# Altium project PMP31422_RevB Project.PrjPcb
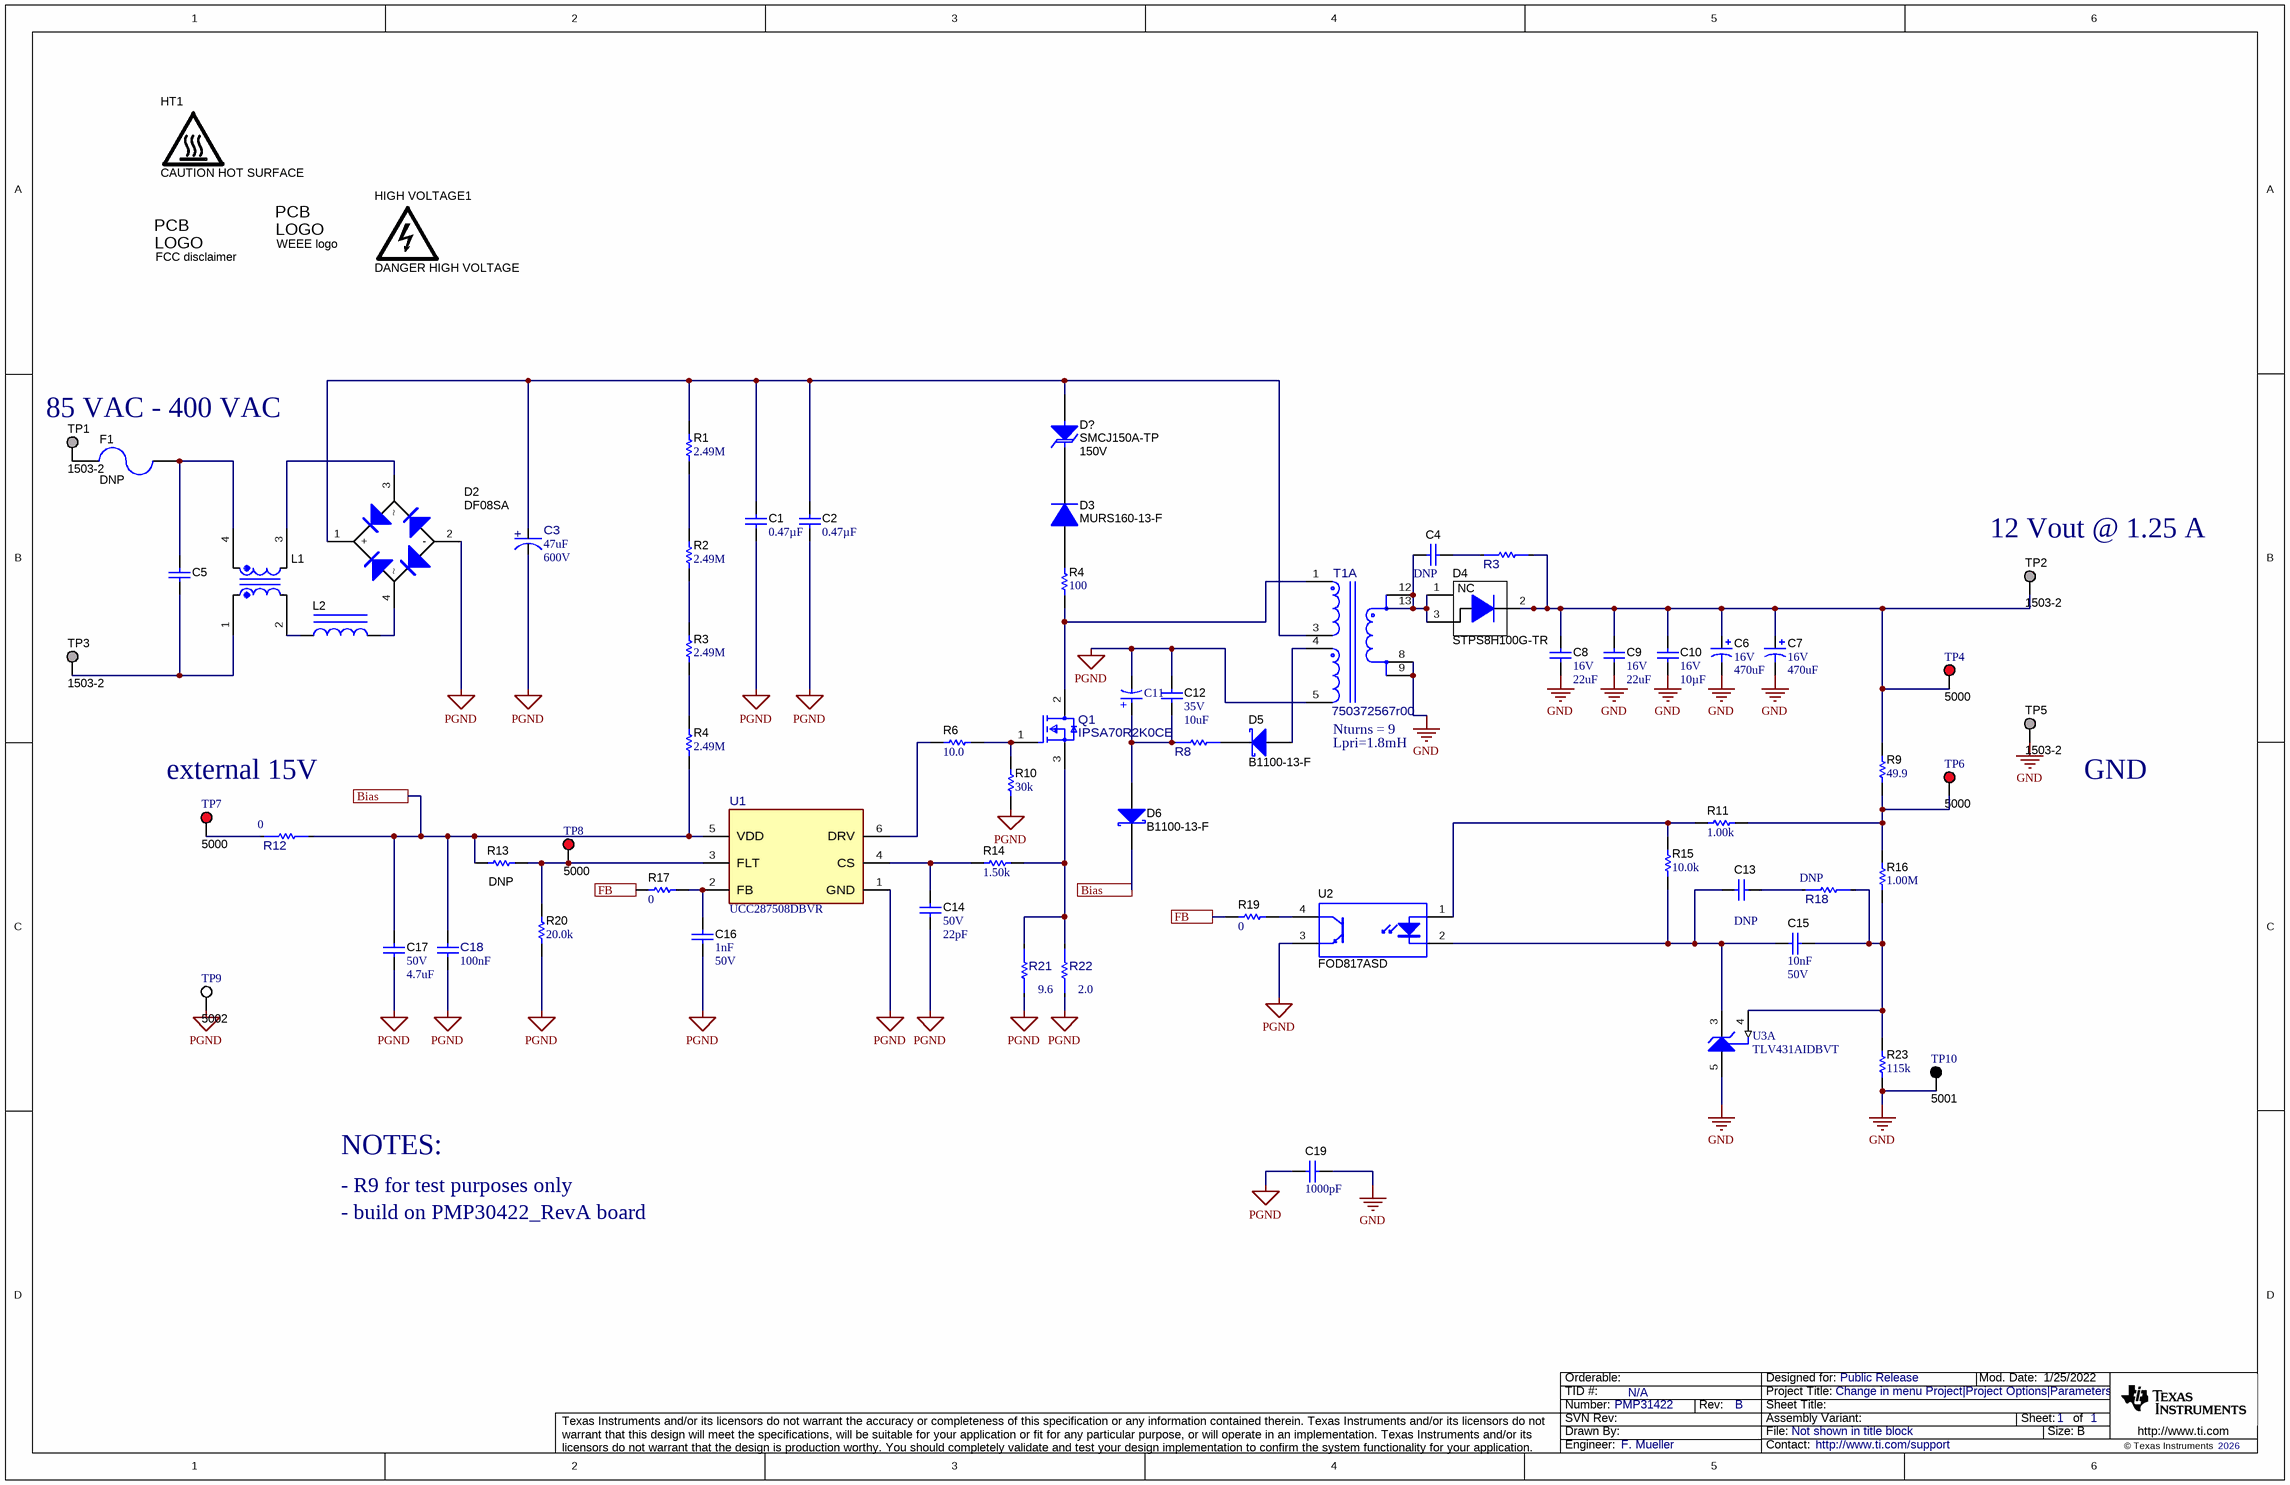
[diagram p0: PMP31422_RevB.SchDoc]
TID: N/A; TechSupport: http://www.ti.com/support; SCH_Rev: B; PRJ_Title: Change in menu Project|Project Options|Parameters; PRJ_Number: PMP31422; PRJ_Engineer: F. Mueller; PRJ_Customer: Public Release; PCB_Rev: A; PCB_Layout: F. Mueller; CopyrightYear: 2026
1 sheet, 70 parts. Net scope: flat (ports and power ports of the same name join across sheets).
Board file: PMP31422_RevA.PcbDoc

## Sheet PMP31422_RevB.SchDoc
size 431 x 279 mm; Date: Not shown in title block; ApprovedBy: Not shown in title block; CheckedBy: Not shown in title block; Author: Not shown in title block; CompanyName: Not shown in title block; Engineer: Not shown in title block; Organization: Not shown in title block; Address1: Not shown in title block; Address2: Not shown in title block; Address3: Not shown in title block; Address4: Not shown in title block; DocumentNumber: 2; Revision: Use project parameter SCH_Rev; SheetNumber: 1; SheetTotal: 1; PageSetup: Record=PageOptions¦CenterHorizontal=True¦CenterVertical=True¦PrintScale=1.00¦XCorrection=1.00¦YCorrection=1.00¦PrintKind=0¦BorderSize=5000000¦LeftOffset=0¦BottomOffset=0¦Orientation=2¦PaperLength=1000¦PaperWidth=1000¦Scale=100¦PaperSource=15¦PrintQuality=600¦MediaType=1¦DitherType=10¦PaperKind=Letter¦PrintScaleMode=1

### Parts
(Parts that share a designator on the sheet are numbered #1, #2 ... from top to bottom, then left to right.)
1  FCC disclaimer  [FCC_disclaimer]  (no BOM)
C1  ValueDisplayed: 0.47µF  [2220]  (hidden comment: 2220Y1K00474KETWS2)
C2  ValueDisplayed: 0.47µF  [2220]  (hidden comment: 2220Y1K00474KETWS2)
C3  ValueDisplayed: 47uF  VDC_V: 600V  [FP-B43541B8476M080_RADIAL-MFG]  (hidden comment: B43541B8476M080)
C4  GRM2165C2A102JA01D  [0805_HV]  (value not drawn)
C5  R474I310050A1K  [Kemet_1800x1100x1900]  (value not drawn)
C6  VDC_V: 16V  ValueDisplayed: 470uF  [PSG_800x800]  (hidden comment: APSG160ELL471MH08S)
C7  VDC_V: 16V  ValueDisplayed: 470uF  [SEPC_F13]  (hidden comment: 16SEPC470M+T)
C8  VDC_V: 16V  ValueDisplayed: 22uF  [1210_280]  (hidden comment: C3225X7R1C226K250AC)
C9  VDC_V: 16V  ValueDisplayed: 22uF  [1210_280]  (hidden comment: C3225X7R1C226K250AC)
C10  VDC_V: 16V  ValueDisplayed: 10µF  [1206_180]  (hidden comment: C3216X7R1C106M160AC)
C11  860040573004  [WCAP-ATUL_D6.3H11]  (value not drawn)
C12  VDC_V: 35V  ValueDisplayed: 10uF  [1206]  (hidden comment: GMK316AB7106KL)
C13  DNPC0603C220J5GACTU  [0603]  (value not drawn)
C14  VDC_V: 50V  ValueDisplayed: 22pF  [0603]  (hidden comment: C0603C220J5GACTU)
C15  Cap_F: 10nF  VDC_V: 50V  [0603]  (hidden comment: GRM188R71H103KA01D)
C16  Cap_F: 1nF  VDC_V: 50V  [0603]  (hidden comment: GRM188R71H102KA01D)
C17  VDC_V: 50V  ValueDisplayed: 4.7uF  [1206_180]  (hidden comment: GRM31CR71H475KA12L)
C18  Cap_F: 100nF  [FP-C0603R104K5RAC_0603-IPC_B]  (hidden comment: C0603R104K5RAC)
C19  ValueDisplayed: 1000pF  [C901_B]  (hidden comment: C901U102MYVDBA7317)
D2  DF08SA  [DF-S]
D3  MURS160-13-F  [SMB]
D4  STPS8H100G-TR  [DDPAK]
D5  B1100-13-F  [SMA]
D6  B1100-13-F  [SMA]
D?  SMCJ150A-TP  value 150V  [SMC]
F1  DNP  [FUSE_372]
HIGH_VOLTAGE1  DANGER HIGH VOLTAGE  [IEC_HighVoltage_Medium]  (no BOM)
HT1  CAUTION HOT SURFACE  [IEC_HotSurface_Medium]  (no BOM)
L1  744821150  [WE-CMB_XS]  (value not drawn)
L2  7447031  [WE-FI_1350x700]  (value not drawn)
Q1  IPSA70R2K0CE  [FP-IPSA70R2K0CE_TO251-3-MFG]
R1  ValueDisplayed: 2.49M  [0805_HV]  (hidden comment: CRCW08052M49FKEA)
R2  ValueDisplayed: 2.49M  [0805_HV]  (hidden comment: CRCW08052M49FKEA)
R3#1  TNPW0805100RBYEN  [FP-TNPW0805100RBYEN_0805-MFG]  (value not drawn)
R3#2  ValueDisplayed: 2.49M  [0805_HV]  (hidden comment: CRCW08052M49FKEA)
R4#1  ValueDisplayed: 100  [1210]  (hidden comment: CRCW1210100RFKEA)
R4#2  ValueDisplayed: 2.49M  [0805_HV]  (hidden comment: CRCW08052M49FKEA)
R6  ValueDisplayed: 10.0  [0805_HV]  (hidden comment: CRCW080510R0FKEA)
R8  RMCF0805ZT0R00  [FP-RMCF0805ZT0R00_0805-MFG]  (value not drawn)
R9  ValueDisplayed: 49.9  [0603]  (hidden comment: CRCW060349R9FKEA)
R10  ValueDisplayed: 30k  [0805_HV]  (hidden comment: CRCW080530K0JNEA)
R11  ValueDisplayed: 1.00k  [0603]  (hidden comment: CRCW06031K00FKEA)
R12  Res_ohm: 0  [FP-RMCF0805ZT0R00_0805-MFG]  (hidden comment: RMCF0805ZT0R00)
R13  DNP  [TBD]
R14  ValueDisplayed: 1.50k  [0603]  (hidden comment: CRCW06031K50FKEA)
R15  ValueDisplayed: 10.0k  [0603]  (hidden comment: RCG060310K0FKEA)
R16  ValueDisplayed: 1.00M  [0603]  (hidden comment: CRCW06031M00FKEA)
R17  ValueDisplayed: 0  [0603]  (hidden comment: RMCF0603ZT0R00)
R18  DNP  [FP-CRCW06030000Z0EAHP_0603-MFG]
R19  ValueDisplayed: 0  [0603]  (hidden comment: RMCF0603ZT0R00)
R20  ValueDisplayed: 20.0k  [0603]  (hidden comment: CRCW060320K0FKEA)
R21  Res_ohm: 9.6  [FP-ERJ-6DQFR30V_0805-MFG]  (hidden comment: ERJ-6DQF9R6)
R22  Res_ohm: 2.0  [FP-ERJ-6DQFR30V_0805-MFG]  (hidden comment: ERJ-6DQF2R0V)
R23  ValueDisplayed: 115k  [0603]  (hidden comment: CRCW0603115KFKEA)
T1  750372567r00  [FP-750372567r00_PTH14-MFG]  (part A of 2)
TP1  1503-2  [Keystone1503-2]
TP2  1503-2  [Keystone1503-2]
TP3  1503-2  [Keystone1503-2]
TP4  5000  [Keystone5000]
TP5  1503-2  [Keystone1503-2]
TP6  5000  [Keystone5000]
TP7  5000  [Keystone5000]
TP8  5000  [Keystone5000]
TP9  5002  [Keystone5002]
TP10  5001  [Keystone5001]
U1  UCC287508DBVR  [DBV0006A-MFG]
U2  FOD817ASD  [N04C]
U3  TLV431AIDBVT  [DBV0005A_N]  (part A of 2)
x1  WEEE logo  [WEEE_Minimum]  (no BOM)

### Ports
Bias, FB

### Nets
GND: C6.2(-) C7.2(-) C8.2 C9.2 C10.2 C19.1 R23.2 T1.8 T1.9 TP5.1 TP10.1 U3.5(ANODE)
PGND: C1.2 C2.2 C3.1(CATHODE) C11.2(N) C12.1 C14.2 C16.2 C17.2 C18.2 C19.2 D2.2(-) R10.1 R20.1 R21.1 R22.1 T1.5 TP9.1 U1.1(GND) U2.3(E)
Bias: C17.1 C18.1 D6.1(K) R4#2.1 R12.2 R13.1 U1.5(VDD) ; port Bias
FB: R17.2 R19.2 ; port FB
NetC1_1: C1.1 C2.1 C3.2(ANODE) D2.1(+) D?.2(A) R1.2 T1.3
NetC4_1: C4.1 R3#1.1
NetC4_2: C4.2 D4.1(NC) D4.3(A) T1.12 T1.13
NetC5_1: C5.1 F1.1 L1.4
NetC5_2: C5.2 L1.1 TP3.1
NetC6_1: C6.1(+) C7.1(+) C8.1 C9.1 C10.1 D4.2(K) R3#1.2 R9.2 TP2.1 TP4.1
NetC11_1: C11.1(P) C12.2 D6.2(A) R8.1
NetC13_1: C13.1 C15.1 R15.1 U2.2(K) U3.3(CATHODE)
NetC13_2: C13.2 R18.1
NetC14_1: C14.1 R14.1 U1.4(CS)
NetC15_2: C15.2 R16.1 R18.2 R23.1 U3.4(REF)
NetC16_1: C16.1 R17.1 U1.2(FB)
NetD2_3: D2.3 L1.3
NetD2_4: D2.4 L2.2
NetD3_1: D3.1(K) D?.1(K)
NetD3_2: D3.2(A) R4#1.2
NetD5_1: D5.1(K) R8.2
NetD5_2: D5.2(A) T1.4
NetF1_2: F1.2 TP1.1
NetL1_2: L1.2 L2.1
NetQ1_1: Q1.1(Gate) R6.2 R10.2
NetQ1_2: Q1.2(Drain) R4#1.1 T1.1
NetQ1_3: Q1.3(Source) R14.2 R21.2 R22.2
NetR1_1: R1.1 R2.2
NetR2_1: R2.1 R3#2.2
NetR3#2_1: R3#2.1 R4#2.2
NetR6_1: R6.1 U1.6(DRV)
NetR9_1: R9.1 R11.2 R16.2 TP6.1
NetR11_1: R11.1 R15.2 U2.1(A)
NetR12_1: R12.1 TP7.1
NetR13_2: R13.2 R20.2 TP8.1 U1.3(FLT)
NetR19_1: R19.1 U2.4(C)

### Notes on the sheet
- 85 VAC - 400 VAC
- (near TP2) 12 Vout @ 1.25 A
- external 15V
- (near T1) Nturns = 9
- (near T1) Lpri=1.8mH
- GND
- NOTES:
- - R9 for test purposes only
- - build on PMP30422_RevA board

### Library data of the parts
1 = CMP-0074847-1: FCC_disclaimer; Library Reference: Logo
C1 C2 = CMP-0086177-1: CAP, CERM, 0.47 µF, 1000 V,+/- 10%, X7R, AEC-Q200 Grade 1, 2220; Manufacturer: Knowles Capacitors; SizeAreaWB_mm2: 53.9; AEC Category: Q200; TaMax_C: 125°C; SizeArea_mm2: 28.5; SizeX_mm: 5.7; SizeZ_mm: 1.35; Value: 0.47uF; AEC Qualified: Y; TaMin_C: -55°C; SizeY_mm: 5; Value2: 1000V; AEC Grade: 1; U/M: EA; Cap_F: 470nF; Polarized: N; VDC_V: 1kV
C3 = CMP-0127623-1: 47 µF 600 V Aluminum Electrolytic Capacitors Radial, Can - Snap-In 2.47Ohm @ 100Hz 5000 Hrs @ 85°C; Manufacturer: TDK; AEC Qualified: No; Cap_F: 47µF; IRMS_A: 600mA; SizeZ_mm: 27.2mm; Tolerance_%: 20%; Esr: 2.47; Leakage Current: 400uA; Life: 5000Hours; Value: 47µF
C4 = CMP-0008094-2: DNP; Manufacturer: MuRata; TaMin_C: -55°C; Polarized: N; TempCo: C0G/NP0; SizeAreaWB_mm2: 6.75; Value1: Unknown; U/M: EA; TaMax_C: 125°C; Tolerance_%: 5%; SizeZ_mm: 1.45; SizeX_mm: 2; SizeY_mm: 1.25; Cap_Case: 0805; SizeArea_mm2: 2.5; Cap_F: 1nF; AEC Category: Q200
C5 = CMP-0074799-2: CAP, Film, 0.1 µF, X1 440 VAC, +/- 10%, AEC-Q200 Grade 1, TH; Manufacturer: Kemet; TaMin_C: -40°C; Polarized: N; SizeAreaWB_mm2: 260.0; Value: 0.1uF; TaMax_C: 110°C; VAC_X: 440; SizeZ_mm: 19.1; SizeX_mm: 18.0; SizeY_mm: 11.0; Cap_Case: 18x11x19mm; Value2: 1000V; SizeArea_mm2: 198.0; AEC Qualified: Y; Cap_F: 100nF; VDC_V: 1kV; AEC Grade: 1; AEC Category: Q200; ValueDisplayed: 0.1µF
C6 = CMP-0012172-1: CAP, Aluminum Polymer, 470 uF, 16 V, +/- 20%, 0.016 ohm, TH; Manufacturer: Chemi-Con; TaMin_C: -55°C; ESR_ohm: 16m; Polarized: Y; U/M: EA; Value: 470uF; TaMax_C: 105°C; Cap_Case: 8x8mm; CompType: Capacitor; AEC Qualified: N; Cap_F: 470µF; IRMS_A: 4A; AEC Category: Q200
C7 = CMP-0012077-2: CAP, Aluminum Polymer, 470 uF, 16 V, +/- 20%, 0.01 ohm, TH; Manufacturer: Panasonic; TaMin_C: -55°C; ESR_ohm: 10m; Polarized: Y; SizeAreaWB_mm2: 144; U/M: EA; Value: 470uF; TaMax_C: 105°C; SizeZ_mm: 13; SizeX_mm: 10; Cap_Case: 10x13mm; SizeArea_mm2: 100; CompType: Capacitor; AEC Qualified: N; Cap_F: 470µF; IRMS_A: 6.1A; AEC Category: Q200
C8 C9 = CMP-0009116-1: CAP, CERM, 22 uF, 16 V, +/- 10%, X7R, 1210; Manufacturer: TDK; TaMin_C: -55°C; ESR_ohm: 2.582m; Polarized: N; SizeAreaWB_mm2: 14.7; Value1: 0.002582 ohm; U/M: EA; Value: 22uF; TaMax_C: 125°C; SizeZ_mm: 2.8; SizeX_mm: 3.2; SizeY_mm: 2.5; SizeArea_mm2: 8; Cap_F: 22µF; IRMS_A: 4.5756A; AEC Category: Q200
C10 = CMP-0082521-1: CAP, CERM, 10 µF, 16 V,+/- 20%, X7R, 1206; Manufacturer: TDK; SizeAreaWB_mm2: 10.92; SizeArea_mm2: 5.12; AEC Qualified: N; AEC Category: Q200; Value: 10uF; TaMax_C: 125°C; SizeZ_mm: 1.8; Green_REACh: Passed; TaMin_C: -55°C; SizeY_mm: 1.6; Green_Lifecycle: Active; U/M: EA; SizeX_mm: 3.2; Cap_Case: 1206
C11 = CMP-0116855-1: WCAP-ATUL Aluminum Electrolytic Capacitor, Radial, THT, D6.3 x H11mm, 100µF, 35V; Manufacturer: Wurth Elektronik; Capacitance Tolerance: 20%; Dissipation Factor: 12%; Endurance: 5000h; Leakage Current: 35uA; Ripple Current: 450mA; Technical Reference: ATDD110101M035DSPA4E000
C12 = CMP-0008821-1: CAP, CERM, 10 uF, 35 V, +/- 10%, X7R, 1206; Manufacturer: Taiyo Yuden; TaMin_C: -55°C; Polarized: N; SizeAreaWB_mm2: 10.92; Value1: Unknown; U/M: EA; Value: 10uF; TaMax_C: 125°C; SizeZ_mm: 1.35; SizeX_mm: 3.2; SizeY_mm: 1.6; SizeArea_mm2: 5.12; Cap_F: 10µF; AEC Category: Q200
C13 = CMP-0006892-1: DNP; Manufacturer: Kemet; TaMin_C: -55°C; Polarized: N; TempCo: C0G/NP0; SizeAreaWB_mm2: 4.68; Value1: Unknown; U/M: EA; TaMax_C: 125°C; Tolerance_%: 5%; SizeZ_mm: 1; SizeX_mm: 1.6; SizeY_mm: 0.8; Value2: 50V; SizeArea_mm2: 1.28; AEC Category: Q200
C14 = CMP-0006892-1: CAP, CERM, 22 pF, 50 V, +/- 5%, C0G/NP0, 0603; Manufacturer: Kemet; TaMin_C: -55°C; Polarized: N; SizeAreaWB_mm2: 4.68; Value1: Unknown; U/M: EA; Value: 22pF; TaMax_C: 125°C; SizeZ_mm: 1; SizeX_mm: 1.6; SizeY_mm: 0.8; SizeArea_mm2: 1.28; AEC Category: Q200
C15 = CMP-0007433-1: CAP, CERM, 0.01 uF, 50 V, +/- 10%, X7R, 0603; Manufacturer: MuRata; TaMin_C: -55°C; Polarized: N; SizeAreaWB_mm2: 4.68; Value1: Unknown; U/M: EA; Value: 0.01uF; TaMax_C: 125°C; SizeZ_mm: 1; SizeX_mm: 1.6; SizeY_mm: 0.8; SizeArea_mm2: 1.28; AEC Category: Q200
C16 = CMP-0007432-1: CAP, CERM, 1000 pF, 50 V, +/- 10%, X7R, 0603; Manufacturer: MuRata; TaMin_C: -55°C; Polarized: N; SizeAreaWB_mm2: 4.68; Value1: Unknown; U/M: EA; Value: 1000pF; TaMax_C: 125°C; SizeZ_mm: 1; SizeX_mm: 1.6; SizeY_mm: 0.8; SizeArea_mm2: 1.28; AEC Category: Q200
C17 = CMP-0008969-2: CAP, CERM, 4.7 uF, 50 V, +/- 10%, X7R, 1206; Manufacturer: MuRata; TaMin_C: -55°C; Polarized: N; SizeAreaWB_mm2: 10.92; Value1: Unknown; U/M: EA; Value: 4.7uF; TaMax_C: 125°C; SizeZ_mm: 1.8; SizeX_mm: 3.2; SizeY_mm: 1.6; Cap_Case: 2220; SizeArea_mm2: 5.12; Cap_F: 4.7µF; AEC Category: Q200
C18 = CMP-0087061-2: CAP CER 0.1UF 50V X7R 0603; Manufacturer: Kemet; TempCo: 15%; SizeZ_mm: 0.87mm; Tolerance_%: 10%; AEC Qualified: No; Symbol Name: SYM-C0603R104K5RAC
C19 = CMP-0009592-2: CAP, CERM, 1000 pF,  V, +/- 20%, Y5V, D7xT5mm; Manufacturer: Kemet; TaMin_C: -40°C; Polarized: N; SizeAreaWB_mm2: 91; Value1: Unknown; U/M: EA; Value: 1000pF; TaMax_C: 125°C; SizeZ_mm: 11; SizeY_mm: 5; Cap_Case: 7x5mm; SizeArea_mm2: 55; Cap_F: 1nF; AEC Category: Q200
D2 = CMP-0029205-3: Diode, Switching-Bridge, 800 V, 1 A, DF-S; Manufacturer: Vishay-Semiconductor; SizeAreaWB_mm2: 98.794; Value1: 1A; Value2: 1.1V; SizeArea_mm2: 62.974; Vr_V: 800V; Value: 800V; AEC Category: Q101; SizeZ_mm: 3.4; TJmax_C: 150°C; Green_Lifecycle: Not Set; SizeX_mm: 7.4; RJC_CperW: 15; Green_REACh: Incomplete; SizeY_mm: 8.51
D3 = CMP-0029028-2: Diode, Ultrafast, 600 V, 1 A, SMB; Manufacturer: Diodes Inc.; Green_REACh: Passed; RJC_CperW: 13; Value1: 1A; Vr_V: 600V; SizeY_mm: 3.81; Green_Lifecycle: Active; TJmax_C: 150°C; SizeArea_mm2: 21.336; AEC Category: Q101; Value2: 1.25V; SizeZ_mm: 2.6; SizeX_mm: 5.6; SizeAreaWB_mm2: 44.156; Value: 600V
D4 = CMP-0028896-3: Diode, Schottky, 100 V, 8 A, DDPAK; Manufacturer: STMicroelectronics; SizeY_mm: 10.16; Green_REACh: Incomplete; Vr_V: 100V; TJmax_C: 175°C; SizeX_mm: 15.245; SizeArea_mm2: 154.8892; AEC Qualified: N; Io_A: 8A; SizeZ_mm: 4.445; SizeAreaWB_mm2: 209.6992; Value: 100V; Value2: 0.71V; RJC_CperW: 1.6; Green_Lifecycle: Not Set; Vf_V: 710mV; AEC Category: Q101
D5 D6 = CMP-0028371-2: Diode, Schottky, 100 V, 1 A, SMA; Manufacturer: Diodes Inc.; Io_A: 1A; SizeZ_mm: 2.87; Green_REACh: Passed; TJmax_C: 150°C; Value: 100V; SizeAreaWB_mm2: 37.3428; Vf_V: 790mV; RJC_CperW: 25; SizeX_mm: 5.59; AEC Category: Q101; SizeArea_mm2: 16.3228; SizeY_mm: 2.92; Value2: 0.79V; Green_Lifecycle: Active
D? = CMP-0005708-3: Diode, TVS, Uni, 150 V, 243 Vc, SMC; Manufacturer: Micro Commercial Components; SizeX_mm: 8.13; Vc: 243V; AEC Category: Q101; SizeY_mm: 6.22; SizeAreaWB_mm2: 83.2686; SizeZ_mm: 2.6; Ppk: 1.5kW; AEC Qualified: N; Ipp: 6.2A; Value1: 1500W; Vbr_Max: 185V; SizeArea_mm2: 50.5686; Vbr_Min: 167V
F1 = CMP-0003555-1: Fuse, 2 A, 250VAC/VDC, TH; Manufacturer: Littelfuse; Irating_A: 2A; VAC_V: 250V
HIGH_VOLTAGE1 = CMP-0074835-1: IEC 61010-1 High Voltage Warning; SymbolCreator: a0412235
HT1 = CMP-0074837-1: IEC 61010-1 Hot Surface Warning; SymbolCreator: a0412235
L1 = CMP-0084275-1: Coupled inductor, 5 mH, 0.22 ohm, TH; Manufacturer: Wurth Elektronik; SizeY_mm: 7.5; DCR_ohm: 0.22; SizeZ_mm: 20.5; AEC Category: Q200; SizeAreaWB_mm2: 161.5; Ind_H: 5mH; SizeX_mm: 15; SizeArea_mm2: 112.5; AEC Qualified: N; Value: 5mH
L2 = CMP-0064732-2: Inductor, Toroid, Powdered Iron, 140 uH, 1 A, 0.11 ohm, TH; Manufacturer: Wurth Elektronik; Irms: 1A @ 40C rise; Green_Lifecycle: Active; SizeAreaWB_mm2: 139.5; DCR_ohm: 0.11; Green_REACh: Passed; Value: 140uH; Imax_A: 1A; SizeZ_mm: 13.5; SizeX_mm: 7; SizeArea_mm2: 94.5; Ind_H: 140µH; AEC Qualified: N; AEC Category: Q200
Q1 = CMP-0127653-1: Trans MOSFET N-CH 700V 4A 3-Pin(3+Tab) TO-251 Tube; Manufacturer: Infineon; AEC Qualified: No; QgTyp_nC: 7.8nC @ 10V; Rdson45_ohm: 1.8; SizeZ_mm: 8.9mm; Vgs_V: 20V; Input Capacitance At Vds: 163pF @ 100V; Number Of Channels: 1; Power_W: 42W; Pulse Drain Current: 6.3A; Reverse Recovery Charge: 800nC; Reverse Recovery Time: 187ns; Rthja Max: 62°C/W; Standoff Height: 1.15mm; Threshold Vgs Max: 3.5V; Threshold Vgs Min: 2.5V; TJmax_C: +150°C; Turn Off Delay Time: 25ns; Turn On Delay Time: 6.4ns; Typ Forward Diode Voltage: 0.9V
R1 R2 R3#2 R4#2 = CMP-0021133-2: RES, 2.49 M, 1%, 0.125 W, 0805; Manufacturer: Vishay-Dale; Power_W: 125mW; TempCo: 100 ppm/C; Value_Code: 2M49; U/M: EA; Value: 2.49Meg; EIA_Code: E96; SizeX_mm: 2; SizeY_mm: 1.25; SizeZ_mm: 1.45; Value2: 0.125W; SizeArea_mm2: 2.5; VDC_V: 150V; AEC Category: Q200
R3#1 = CMP-0091372-1: Manufacturer: Vishay; VDC_V: 150V; TempCo: 10ppm/°C; Power_W: 200mW; Tolerance_%: 0.1%; AEC Grade: Grade 0; SizeZ_mm: 0.55mm; Res_ohm: DNP; Value: DNP; AEC Qualified: Yes
R4#1 = CMP-0082536-1: RES, 100, 1%, 0.5 W, AEC-Q200 Grade 0, 1210; Manufacturer: Vishay-Dale; Power_W: 500mW; TempCo: 100 ppm/C; SizeAreaWB_mm2: 14.7; Value_Code: 100R; Value: 100; EIA_Code: E96; SizeX_mm: 3.2; SizeY_mm: 2.5; SizeZ_mm: 1.35; Value2: 0.5W; SizeArea_mm2: 8; AEC Qualified: Y; VDC_V: 200V; AEC Grade: 0; AEC Category: Q200
R6 = CMP-0020847-3: RES, 10.0, 1%, 0.125 W, AEC-Q200 Grade 0, 0805; Manufacturer: Vishay-Dale; Power_W: 125mW; TempCo: 100 ppm/C; Value_Code: 10R0; Value: 10.0; EIA_Code: E96; Res_ohm: 10; SizeX_mm: 2; SizeY_mm: 1.25; SizeZ_mm: 1.45; Value2: 0.125W; SizeArea_mm2: 2.5; AEC Qualified: Y; VDC_V: 150V; AEC Category: Q200; AEC Grade: 0
R8 = CMP-0089632-1: 0 Ohms Jumper 0.125W, 1/8W Chip Resistor 0805 (2012 Metric) Automotive AEC-Q200 Thick Film; Manufacturer: Stackpole Electronics; TempCo: 200ppm/°C; SizeZ_mm: 0.65mm; AEC Grade: Grade 0; AEC Qualified: Yes; Res_ohm: 0; Power_W: 125mW; VDC_V: 150V
R9 = CMP-0022448-2: RES, 49.9, 1%, 0.1 W, 0603; Manufacturer: Vishay-Dale; Power_W: 100mW; TempCo: 100 ppm/C; Value_Code: 49R9; U/M: EA; Value: 49.9; EIA_Code: E96; SizeX_mm: 1.6; SizeY_mm: 0.8; SizeZ_mm: 1; Value2: 0.1W; SizeArea_mm2: 1.28; VDC_V: 75V; AEC Category: Q200
R10 = CMP-0020524-1: RES, 30 k, 5%, 0.125 W, 0805; Manufacturer: Vishay-Dale; Power_W: 125mW; TempCo: 200 ppm/C; Value_Code: 30k0; U/M: EA; Value: 30k; EIA_Code: E24; SizeX_mm: 2; SizeY_mm: 1.25; SizeZ_mm: 1.45; Value2: 0.125W; SizeArea_mm2: 2.5; VDC_V: 150V; AEC Category: Q200
R11 = CMP-0022109-2: RES, 1.00 k, 1%, 0.1 W, 0603; Manufacturer: Vishay-Dale; Power_W: 100mW; TempCo: 100 ppm/C; Value_Code: 1k00; U/M: EA; Value: 1.00k; EIA_Code: E96; Res_ohm: 1k; SizeX_mm: 1.6; SizeY_mm: 0.8; SizeZ_mm: 1; Value2: 0.1W; SizeArea_mm2: 1.28; VDC_V: 75V; AEC Category: Q200
R12 = CMP-0089632-1: 0 Ohms Jumper 0.125W, 1/8W Chip Resistor 0805 (2012 Metric) Automotive AEC-Q200 Thick Film; Manufacturer: Stackpole Electronics; TempCo: 200ppm/°C; SizeZ_mm: 0.65mm; AEC Grade: Grade 0; AEC Qualified: Yes; Power_W: 125mW; VDC_V: 150V
R13 = Resistor: Manufacturer: Used in BOM report; U/M: EA
R14 = CMP-0022126-3: RES, 1.50 k, 1%, 0.1 W, 0603; Manufacturer: Vishay-Dale; Power_W: 100mW; TempCo: 100 ppm/C; Value_Code: 1k50; U/M: EA; Value: 1.50k; EIA_Code: E96; Res_ohm: 1.5k; SizeX_mm: 1.6; SizeY_mm: 0.8; SizeZ_mm: 1; Value2: 0.1W; SizeArea_mm2: 1.28; VDC_V: 75V; AEC Category: Q200
R15 = CMP-0023337-1: RES, 10.0 k, 1%, 0.1 W, 0603; Manufacturer: Vishay Draloric; Power_W: 100mW; TempCo: 100 ppm/C; Value_Code: 10k0; U/M: EA; Value: 10.0k; EIA_Code: E96; Res_ohm: 10k; SizeX_mm: 1.6; SizeY_mm: 0.8; SizeZ_mm: 1; Value2: 0.1W; SizeArea_mm2: 1.28; AEC Qualified: N; VDC_V: 75V; AEC Category: Q200
R16 = CMP-0022138-4: RES, 1.00 M, 1%, 0.1 W, AEC-Q200 Grade 0, 0603; Manufacturer: Vishay-Dale; Power_W: 100mW; TempCo: 100 ppm/C; Value_Code: 1M00; Value: 1.00Meg; EIA_Code: E96; Res_ohm: 1M; SizeX_mm: 1.6; SizeY_mm: 0.8; SizeZ_mm: 1; Value2: 0.1W; SizeArea_mm2: 1.28; AEC Qualified: Y; VDC_V: 75V; AEC Category: Q200; AEC Grade: 0
R17 R19 = CMP-0023343-2: RES, 0, 1%, 0.1 W, AEC-Q200 Grade 0, 0603; Manufacturer: Stackpole Electronics Inc; Power_W: 100mW; TempCo: ppm/C; U/M: EA; Value: 0; SizeX_mm: 1.6; SizeY_mm: 0.8; SizeZ_mm: 1; Value2: 0.1W; SizeArea_mm2: 1.28; AEC Qualified: Y; AEC Category: Q200
R18 = CMP-0122893-1: Manufacturer: Vishay; AEC Grade: Grade 0; AEC Qualified: Yes; SizeZ_mm: 0.55mm; Power: 250mW
R20 = CMP-0022204-3: RES, 20.0 k, 1%, 0.1 W, 0603; Manufacturer: Vishay-Dale; Power_W: 100mW; TempCo: 100 ppm/C; Value_Code: 20k0; U/M: EA; Value: 20.0k; EIA_Code: E96; Res_ohm: 20k; SizeX_mm: 1.6; SizeY_mm: 0.8; SizeZ_mm: 1; Value2: 0.1W; SizeArea_mm2: 1.28; VDC_V: 75V; AEC Category: Q200
R21 = CMP-0037657-1: Res Thick Film 0805 9.6 Ohm 1%; Manufacturer: Panasonic; AEC Grade: Grade 0; AEC Qualified: Yes; Power_W: 500mW; SizeZ_mm: 0.7mm; TempCo: 0/+100ppm/°C
R22 = CMP-0037657-1: Res Thick Film 0805 2 Ohm 1%; Manufacturer: Panasonic; AEC Grade: Grade 0; AEC Qualified: Yes; Power_W: 500mW; SizeZ_mm: 0.7mm; TempCo: 0/+100ppm/°C
R23 = CMP-0022012-1: RES, 115 k, 1%, 0.1 W, 0603; Manufacturer: Vishay-Dale; Power_W: 100mW; TempCo: 100 ppm/C; U/M: EA; Value: 115k; EIA_Code: E96; SizeX_mm: 1.6; SizeY_mm: 0.8; SizeZ_mm: 1; Value2: 0.1W; SizeArea_mm2: 1.28; VDC_V: 75V; AEC Category: Q200
T1 = CMP-0128239-1: TRANSFORMER; Manufacturer: Wurth; DCR_ohm: 1.04; Ind_H: 1.8mH; Ns1toNp: 9:1; Rsec1_ohm: 30m; SizeZ_mm: 16mm; AEC Qualified: No; Frequency_Fixed: 200kHz; Voltage_Isolation_Vrms: 3.75kV
TP1-TP3 TP5 = CMP-0055114-1: Terminal, Turret, TH, Double; Manufacturer: Keystone; CT: FALSE; Green_REACh: Passed; CompType: Turret Terminal; Green_Lifecycle: Active
TP4 TP6-TP8 = CMP-0055137-2: Test Point, Miniature, Red, TH; Manufacturer: Keystone Electronics; Green_REACh: Passed; Green_Lifecycle: Active; ContactFinish: Silver; CNHeader: FALSE; CT: TRUE
TP9 = CMP-0055139-1: Test Point, Miniature, White, TH; Manufacturer: Keystone; CNHeader: FALSE; Green_Lifecycle: Active; Green_REACh: Passed; ContactFinish: Silver; CT: TRUE
TP10 = CMP-0055138-1: Test Point, Miniature, Black, TH; Manufacturer: Keystone; CNHeader: FALSE; Green_Lifecycle: Active; Green_REACh: Passed; ContactFinish: Silver; CT: TRUE
U1 = CMP-0121343-1: Current-Mode Flyback Controller with Secondary-Side Regulation (SSR) for Off-Line Applications; Manufacturer: Texas Instruments; SizeZ_mm: 1.45mm; AEC Qualified: No; AEC Grade: NA; Max Duty Cycle: 80%; Max Supply Voltage: 26V; Min Supply Voltage: 10V; Nominal Supply Current: 2mA; Number Of Outputs: 1; Standoff Height: 0mm; Switching Frequency: 100kHz; TJmax_C: +125°C
U2 = CMP-0006181-3: Optocoupler, 5 kV, 80-160% CTR, SMT; Manufacturer: Fairchild Semiconductor; CTR (Max): 160%; CTR (Min): 80%; Voltage_Isolation_Vrms: 5kV
U3 = CMP-0032942-1: Low Voltage Adjustable Precision Shunt Regulator, 39 ppm / degC, 15 mA, -40 to 85 degC, 5-pin SOT-23 (DBV), Green (RoHS & no Sb/Br); Manufacturer: Texas Instruments; VO Adj(Max)(V): 6; Initial Accuracy @ 25/deg C(%): 1; Temp Coeff(Typ)(ppm/ degree C): 39; VO Adj(Min)(V): 1.24; Min Iz for Regulation(uA): 80; SubFamily: Shunt Voltage Reference; Rating: Catalog; Temp Coeff(Max)(ppm/ degree C): 129; Iout/Iz(Max)(mA): 15
x1 = CMP-0074769-1

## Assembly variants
001: not fitted FID1 FID2 FID3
